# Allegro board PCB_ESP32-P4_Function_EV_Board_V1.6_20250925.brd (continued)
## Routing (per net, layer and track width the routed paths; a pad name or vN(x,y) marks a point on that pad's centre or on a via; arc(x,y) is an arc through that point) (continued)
USB_5V: length 44.1
  TOP w1.5: SW3.2 35.42,14.34 38.95,14.34 41.9,11.39 49.14,11.39
  BOTTOM w0.254: C80.1 32.42,19.95
  BOTTOM w0.381: Q2.4 45.92,12.77 46.31,13.15 47.69,13.15 v1(48.43,12.41)
  BOTTOM w1: C79.1 32.42,17.38 SW3.2
  BOTTOM w1.5: 37.76,12.53 37.76,13.33 36.54,14.54 35.22,14.54 SW3.2 29.68,14.65 26,14.65 24.76,13.4
  vias: v1(49.11,12.41) v1(49.8,12.39)
USB_DM: length 24
  TOP w0.127: R221.2 9.82,18.83 9.82,21.38 16.65,28.21 16.65,36.19 18.62,38.15 18.98,38.15 19,38.17 U4.49
USB_DM_A: length 7.4
  TOP w0.127: R221.1 9.87,17.31 9.87,17.13 v1(9.67,16.93) 9.85,16.75 9.85,16.51 R178.2
  BOTTOM w0.127: v1(9.67,16.93) 9.85,16.75 9.85,14.46 9.66,14.26 D22.2 9.31,14.12 9.83,13.6 9.83,13.19 J18.2
USB_DM_C: length 25.5
  TOP w0.127: R178.1 9.87,14.95 9.87,14.52 10.3,14.09 21.81,14.09 25.75,10.15 25.75,9.09 25.32,8.66 25.31,8.66 ; 25.31,8.66 25.76,8.2 25.76,7.57 25.67,7.48 J15.9 v1(25.67,5.76) ; 25.31,8.66 D14.2 ; J15.7 v1(24.67,5.76)
  BOTTOM w0.127: v1(25.67,5.76) v1(24.67,5.76)
USB_DP: length 24
  TOP w0.127: U4.50 19,37.83 18.98,37.85 18.75,37.85 18.35,37.45 18.35,37.02 R234.1 17.53,36.2 17.1,36.2 16.96,36.06 16.96,28.08 10.13,21.25 10.13,21.09 10.37,20.85 10.37,20.5 10.13,20.26 10.13,18.86 10.38,18.6 R220.2
USB_DP_A: length 7.4
  TOP w0.127: R179.2 10.16,16.54 10.16,16.72 v1(10.35,16.92) 10.18,17.1 10.18,17.32 10.44,17.59 R220.1
  BOTTOM w0.127: J18.3 10.16,13.16 10.16,13.59 10.69,14.12 D21.2 10.35,14.27 10.15,14.47 10.15,16.77 10.3,16.92 v1(10.35,16.92)
USB_DP_C: length 26.1
  TOP w0.127: D16.2 26.49,8.66 ; 26.49,8.66 26.07,8.24 26.07,7.57 26.17,7.48 J15.10 26.17,5.55 25.87,5.26 25.45,5.26 25.17,5.55 J15.8 ; 26.49,8.66 26.48,8.66 26.05,9.08 26.05,10.28 21.94,14.39 10.43,14.39 10.18,14.65 10.18,14.95 R179.1
VMID: length 2.8
  TOP w0.254: C37.2 68.39,54.4 67.53,53.53 66.87,53.53 66.57,53.24 U3.16
XTAL_N: length 2.4
  TOP w0.127: U4.99 30.51,44.12 R70.1
XTAL_P: length 2.2
  TOP w0.127: U4.100 30.54,44.48 30.78,44.24 R67.1
N16934509: length 3.1
  TOP w0.127: C28.1 34.04,45.54 Y2.1 34.03,44.24 R67.2
N16934523: length 5
  TOP w0.127: R70.2 34.59,43.37 Y2.3 35.55,42.42 C45.1
N17578381: length 1.2
  TOP w0.381: D12.1 41.22,16.09 R175.1
N18064827: length 4.7
  TOP w0.18: U4.51 19.86,37.48 v1(19.89,37.5)
  BOTTOM w0.254: v1(19.89,37.5) 20.35,37.96 C100.1 C99.1 C98.1 23.27,38.89 R233.1
N18110516: length 7.4
  TOP w0.127: Y1.2 36.18,50.73 C19.1 36.01,49.22 36.01,48.9 R58.1 34.19,47.08 32.1,47.08 R61.2
N18110531: length 6.5
  TOP w0.127: Y1.1 33.16,50.73 C18.1 33.34,49.21 33.34,48.97 R58.2 34.2,47.69 33.9,47.39 32.12,47.39 R59.2
N18193754: length 5.9
  TOP w0.635: U7.4 33.28,31.42 C54.1 34.37,31.42 35.47,30.32 36.45,30.32 R127.2
N18193822: length 2.1
  TOP w0.635: U7.3 33.61,29.15 L1.1
N18248775: length 2.5
  TOP w0.254: R151.2 U9.3 20.51,22.04 TP28.1
N18251395: length 4.7
  BOTTOM w0.127: R224.2 41.01,12.41 40.75,12.68 Q6.6 40.75,13.28 40.61,13.43 40.22,13.43 40.1,13.3 Q6.5 Q6.2
N18251818: length 5.7
  BOTTOM w0.127: Q6.3 39.45,11.15 39.32,11.28 36.93,11.28 35.92,12.29 Q7.1 34.39,12.47 R225.2
N18253640: length 4.6
  BOTTOM w0.127: R217.2 27.3,12.49 27.06,12.73 Q5.6 27.06,13.34 26.91,13.48 26.56,13.48 26.41,13.33 Q5.5 Q5.2
N18253683: length 5.8
  BOTTOM w0.127: Q5.3 25.76,11.31 25.49,11.57 22.9,11.57 22.15,12.32 Q4.1 22.15,13.92 R216.2
N18255493: length 1.9
  TOP w0.254: R180.2 24.17,8.38 J15.6
N18255499: length 2.1
  TOP w0.254: R182.2 27.17,7.96 J15.12
N18256275: length 1.8
  TOP w0.254: R184.2 39.21,8.5 J19.6
N18256281: length 2
  TOP w0.254: J19.12 42.21,8.07 R183.2
N18262730: length 3.3
  TOP w0.254: R170.1 R172.2 C69.2 43.99,16.21 44.37,16.59 U11.5
N18262736: length 7.9
  TOP w0.254: v1(45.86,14.88) 45.47,14.48 R172.1 C69.1
  BOTTOM w0.254: v1(45.86,14.88) 47.27,16.29 v1(51.28,16.29)
N18262777: length 2.2
  TOP w0.127: R173.2 48.26,15.53 48.26,15.7 47.38,16.59 U11.1
N18266990: length 4.9
  BOTTOM w0.381: J17.4 71.54,16.33 69.39,16.33 C115.1
N18266994: length 5
  BOTTOM w0.381: C116.1 78.3,13.91 75.38,13.91 74.16,15.13
N18267072: length 13.6
  BOTTOM w0.254: J17.10 70.94,5.37 70.94,10.17 66.31,14.79 R223.1
N18267076: length 15.3
  BOTTOM w0.254: J17.11 77.61,4.47 R222.1
N18267340: length 3.1
  TOP w0.127: R143.2 68.49,27.98 68.49,27.63 69.26,26.86 U8.17
N18267342: length 2.7
  TOP w0.127: U8.18 69.1,26.46 68.09,27.47 68.09,27.55 R144.2
N18267344: length 2.5
  TOP w0.127: U8.19 68.94,26.06 67.87,27.13 67.67,27.13 R150.2
N18267350: length 1.8
  TOP w0.127: U8.14 70.86,27.84 70.3,28.41 R139.2
N18267444: length 3.3
  TOP w0.254: v1(71.17,22.3) 71.26,22.39 U8.28
  BOTTOM w0.381: C113.1 70.44,22.56 C111.1 70.91,22.57 v1(71.17,22.3)
N18267472: length 2.1
  TOP w0.127: U8.10 72.46,27.79 73.45,28.77 73.45,28.87 R142.2
N18299901: length 2
  TOP w0.127: U3.18 65.77,53.48 66.38,54.09 66.38,54.35 C32.2
N18299903: length 2.3
  TOP w0.127: U3.17 66.17,53.5 66.69,54.02 66.97,54.02 C34.2
N18300035: length 2.6
  TOP w0.127: U3.1 63.65,52.2 63.18,52.67 C24.1 R52.2
N18300076: length 2.5
  TOP w0.127: U3.19 65.37,54.52 C27.1 R62.2
N18300564: length 4.1
  TOP w0.127: TP20.1 56.66,55.49 55.74,55.49 55.24,55.99 J7.2
N18300580: length 6.3
  TOP w0.254: v1(58.56,57.09) R65.2 C36.2 R73.1 ; v1(58.56,54.19) 57.95,54.19 R63.2
  POWER w0.254: v1(58.56,54.19) v1(58.56,57.09)
N18302373: length 2.9
  TOP w0.254: C41.1 C40.2 68.87,50.76 68.24,51.4 U3.13
N18302385: length 3.4
  TOP w0.254: C38.1 C39.2 68.64,49.85 68.34,50.16 68.34,50.66 68,51 U3.12
N18302434: length 1
  TOP w0.254: C40.1 R84.1
N18302436: length 1
  TOP w0.254: C39.1 R83.1
N18379689: length 3.8
  TOP w0.127: R158.2 76.49,25.08 R159.1 77.16,24.62 Y3.1 77.88,25.97 C64.1
N18379734: length 5.6
  TOP w0.127: C68.1 79.38,21.47 Y3.3 78.49,23.71 77.05,23.71 R159.2 76.54,24.22 R161.2
N18399134: length 4.3
  BOTTOM w0.127: R176.2 Q2.2 Q2.5 46.57,12.44 46.7,12.56 47.1,12.56 47.22,12.44 Q2.6
N18399180: length 6.2
  BOTTOM w0.127: 49.03,8.33 Q3.1 ; 49.03,8.33 R177.2 ; 49.03,8.33 46.49,8.33 45.92,8.9 Q2.3
N18405255: length 2
  TOP w0.254: R185.2 54.25,8.12 J20.6
N18405261: length 1.9
  TOP w0.254: R186.2 57.25,8.39 J20.12
N18412230: length 2.2
  TOP w0.127: J5.11 7.66,57.5 R9.2
N18412242: length 2.2
  TOP w0.127: R8.2 7.66,58.5 J5.12
N18422156: length 1.8
  TOP w0.254: U10.2 64.57,44.96 64.18,45.35 C62.1
N18423897: length 8.9
  TOP w0.635: C78.2 75.81,48.03 TP32.1 75.53,48.02 73.58,46.07 L3.1 ; C78.2 C77.2 ; C78.2 77.91,48.03 78.4,48.52 J16.1
N18423915: length 9.2
  TOP w0.635: C81.1 C78.1 ; C78.1 76.19,47.01 TP31.1 74.72,45.54 74.72,44.67 73.8,43.75 L2.1 ; C78.1 77.85,47.01 78.35,46.52 J16.2
N18424033: length 1
  TOP w0.254: 63.08,44.44 C59.2
N18424043: length 1
  TOP w0.254: 63.08,43.57 C58.2
N18497724: length 3.2
  TOP w0.127: J9.13 v1(9.87,38.23)
  BOTTOM w0.127: R106.2 9.24,37.61 v1(9.87,38.23)
N18497727: length 3.3
  TOP w0.127: J9.14 v1(9.87,39.23)
  BOTTOM w0.127: v1(9.87,39.23) 9.11,38.47 R101.2
N18604768: length 1.4
  TOP w0.127: R226.1 52.73,42.91 U5.3
N18792940: length 3
  TOP w0.18: 20.18,36.58 20.18,35.91 v1(20.06,35.8)
  BOTTOM w0.254: R232.1 C118.1 20.06,35.62 v1(20.06,35.8)

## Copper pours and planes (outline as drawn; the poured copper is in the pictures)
AGND on TOP: 56.76,38.5 56.45,38.8 56.45,50.28 53.56,53.18 51.48,53.18 50.46,54.19 50.46,57.5 51.86,58.89 66.77,58.89 71.47,54.19 82.37,54.19 83.28,53.32 84.5,53 86,53 87.06,52.56 87.5,51.5 87.5,42.56 69.76,42.56 65.7,38.5 ; 8 cut-outs
AGND on BOTTOM, GND, POWER: 56.76,38.5 56.45,38.8 56.45,50.28 53.56,53.18 51.48,53.18 50.46,54.19 50.46,57.5 51.86,58.89 66.77,58.89 71.47,54.19 82.37,54.19 83.28,53.32 84.5,53 86,53 87.06,52.56 87.5,51.5 87.5,42.56 69.76,42.56 65.7,38.5
GND on TOP: 2,0.5 0.94,0.94 0.5,2 0.5,72 0.94,73.06 2,73.5 80.5,73.5 81.56,73.06 82,72 82,55.5 82.73,53.73 84.5,53 86,53 87.06,52.56 87.5,51.5 87.5,2 87.06,0.94 86,0.5 ; 20 cut-outs
GND on BOTTOM: 2,0.5 0.94,0.94 0.5,2 0.5,72 0.94,73.06 2,73.5 80.5,73.5 81.56,73.06 82,72 82,55.5 82.73,53.73 84.5,53 86,53 87.06,52.56 87.5,51.5 87.5,2 87.06,0.94 86,0.5 ; 31 cut-outs
GND on GND: 2,0.5 0.94,0.94 0.5,2 0.5,72 0.94,73.06 2,73.5 80.5,73.5 81.56,73.06 82,72 82,55.5 82.73,53.73 84.5,53 86,53 87.06,52.56 87.5,51.5 87.5,2 87.06,0.94 86,0.5
GND on POWER: 2,0.5 0.94,0.94 0.5,2 0.5,72 0.94,73.06 2,73.5 80.5,73.5 81.56,73.06 82,72 82,55.5 82.73,53.73 84.5,53 86,53 87.06,52.56 87.5,51.5 87.5,2 87.06,0.94 86,0.5 ; 1 cut-out
GND_EARTH on TOP, BOTTOM, GND, POWER: 2,0.5 0.94,0.94 0.5,2 0.5,12.16 4.05,12.16 6.57,9.64 13.25,9.64 15.76,12.16 17.57,12.16 19.19,10.53 19.19,9.31 21.71,6.8 21.71,3.44 29.12,3.44 29.12,6.82 29.61,7.31 36.26,7.31 36.74,6.82 36.74,3.44 44.16,3.44 44.16,6.9 44.53,7.27 51.31,7.27 51.78,6.8 51.78,3.44 59.22,3.44 59.22,7.03 59.66,7.46 64.13,7.46 64.13,0.5
VBUS_OUT on TOP: 19.43,17.91 19.78,17.91 20.31,17.39 20.31,16.09 20.13,15.92 19.12,15.92 18.79,16.25 18.79,17.26
VBUS_OUT on TOP: 5.35,17.34 6.75,17.34 6.9,17.19 6.9,14.6 8.04,13.45 8.04,11.57 7.48,11.01 5.81,11.01 5.15,11.67 5.15,17.14
VCC_5V on TOP: 44.82,17.72 42.56,17.72 42.33,17.95 42.33,18.96 42.59,19.21 44.86,19.21 45.16,18.9 45.16,18.07
VCC_5V on TOP: 13.56,20.41 15.01,20.41 15.26,20.15 15.26,19.42 14.91,19.06 13.61,19.06 13.38,19.29 13.38,20.23
VCC_5V on POWER: 57.24,42.54 58.13,42.54 58.33,42.33 58.33,41.93 58.16,41.75 57.22,41.75 56.99,41.98 56.99,42.28
VCC_5V on POWER: 13.52,20.41 14.42,20.41 14.8,20.03 14.8,19.65 14.35,19.19 13.53,19.19 13.35,19.36 13.35,20.24
ESP_3V3 on TOP: 77.78,72.84 79.74,72.84 79.89,72.69 79.89,71.85 79.56,71.52 77.88,71.52 77.63,71.77 77.63,72.69
ESP_3V3 on TOP: 52.43,13.06 51.51,13.06 51.31,13.27 51.31,15.12 51.51,15.32 52.59,15.32 52.66,15.26 52.66,13.29
ESP_3V3 on BOTTOM: 46.73,40.43 46.73,36.77 48.25,38.29 48.25,38.9
ESP_3V3 on BOTTOM: 46.76,52.09 46.76,49.05 48.14,50.42 48.14,50.71
ESP_3V3 on BOTTOM: 52.31,12.83 51.59,12.83 51.31,13.11 51.31,14.24 51.45,14.38 52.55,14.38 52.71,14.23 52.71,13.23
ESP_3V3 on BOTTOM: 46.9,27.32 47.39,26.84 47.39,25.85 47.11,25.57 45.43,25.57 45.38,25.62 45.38,26.13 46.57,27.32
ESP_3V3 on BOTTOM: 52.67,66.46 53.74,66.46 53.91,66.28 53.91,65.14 53.66,64.89 52.77,64.89 52.39,65.27 52.39,66.18
ESP_3V3 on BOTTOM: 27.88,38.34 28.44,38.34 28.48,38.3 28.48,37.12 28.26,36.9 26.74,36.9 26.56,37.07 26.56,38.22 26.97,38.62 27.6,38.62
ESP_3V3 on POWER: 52.11,66.49 53.66,66.49 53.86,66.28 53.86,65.24 53.64,65.01 52.47,65.01 51.78,65.7 51.78,66.16
ESP_3V3 on POWER: 47.26,26.15 47.26,25.77 46.9,25.42 45.61,25.42 45.33,25.7 45.33,26.23 45.73,26.62 46.79,26.62
ESP_3V3 on POWER: 26.91,46.78 29.12,44.57 29.12,37.76 28.26,36.9 20.03,36.9 19.62,37.3 19.62,45.33 20.95,46.65 21.07,46.78
USB0_5V on TOP: 52.44,9.97 52.98,9.97 53.46,9.49 53.46,7.58 53.31,7.43 52.67,7.43 52.04,8.07 52.04,9.57
USB0_5V on BOTTOM: 50.84,11.12 53.03,11.12 53.33,10.81 53.33,8.99 53.13,8.79 52.15,8.79 50.77,10.18 50.77,11.04
USB1_5V on TOP: 37.73,9.92 38.24,9.92 38.8,9.36 38.8,7.81 38.37,7.38 37.84,7.38 37.18,8.04 37.18,9.36
USB1_5V on BOTTOM: 36.52,10.73 37.4,10.73 38.62,9.52 38.62,8.68 38.47,8.52 36.57,8.52 36.44,8.65 36.44,10.66
USB2_5V on TOP: 23.61,9.41 23.61,7.71 23.33,7.43 22.83,7.43 22.16,8.09 22.16,8.91 21.89,9.18 21.89,9.77 22.06,9.95 23.08,9.95
USB2_5V on BOTTOM: 22.8,10.81 23.49,10.81 23.66,10.63 23.66,8.98 23.28,8.6 21.68,8.6 21.63,8.65 21.63,9.64
USB_5V on TOP: 48.33,12.74 49.9,12.74 50.1,12.54 50.1,11.17 49.57,10.63 48.83,10.63 47.69,11.78 47.69,12.11
USB_5V on BOTTOM: 25.54,14.21 25.97,13.78 25.97,12.49 25.47,11.98 23.69,11.98 23.64,12.03 23.64,13.35 24.5,14.21
USB_5V on BOTTOM: 48.28,12.74 49.95,12.74 50.13,12.56 50.13,11.8 49.55,11.22 48.5,11.22 48.12,11.6 48.12,12.59
USB_5V on BOTTOM: 37.15,13.3 39.56,13.3 39.69,13.17 39.69,12.49 39.64,12.44 38.8,12.44 38.14,11.78 37.43,11.78 37,12.21 37,13.15
N18262736 on TOP: 52.59,15.89 50.16,15.89 50.09,15.96 50.09,19.49 50.22,19.61 52.07,19.61 52.73,18.95 52.73,16.04
N18262785 on TOP: 49.23,17.46 48.37,17.46 48.31,17.51 48.31,17.91 48.13,18.09 46.62,18.09 46.56,18.15 46.56,18.82 46.59,18.85 47.65,18.85 48.36,19.56 49.22,19.56 49.28,19.5 49.28,17.51

Small or netless copper shapes (teardrops, artwork), in the pictures only: 1 on POWER

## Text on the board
Ref Des/Silkscreen Bottom: IO36 | IO34 | R198 | IO37 | R196 | IO38 | VO2 | VO3 | VO1 | VO4 | RTC_Battery: | MICRO SD CARD | SD_VDD | CMD | CLK | D0 | D1 | D2 | D3 | GND | SD2: | - | +
Ref Des/Silkscreen Top: 3V3 | 5V | HOST | 7 | U0TXD | GND | 8 | 37 | 23 | U0RXD | USB HS | 38 | OC | USB | 22 | 21 | DEVICE | 20 | 5 | 6 | 4 | 3 | (1) | NC | 2 | USB Serial/JTAG | (0) | 36 | (IO24&IO25) | 32 | IO35 | EN | 33 | 54 | 26 | 48 | 46 | 53 | (IO26&IO27) | USB FS | 27 | 47 | NC(45) | MICN | MICP | TX0 | RX0 | BOOT | PROG_C6 | CMD | SD1: | D1 | CLK | SPK+ | SPK- | DET | D3 | D0 | D2 | OFF | ON | ESP32-P4 | Function_EV_Board | V1.6 | RST | MIC | SPK | MIPI | CAMERA | DISPLAY
User.5: FIGURE | SIZE | 0.254 | 0.89 | 0.92 | 1.016 | 1.02 | 1.63 | 1.7 | 2.3 | 3.0 | 0.6 | 1.0 | 3.25 | 1.4x0.6 | 1.7x0.6 | DRILL CHART: TOP to BOTTOM | ALL UNITS ARE IN MILLIMETERS | PLATED | NON-PLATED | QTY | 1247 | 8 | 4 | 1 | 45 | 2 | 3 | 6
